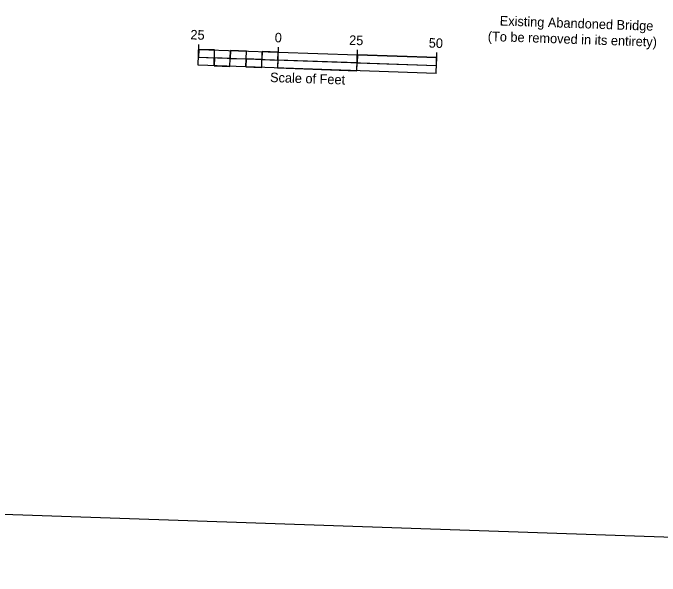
# Model space of a CAD drawing. Extents: x 2191309 to 2193046, y 863659 to 865133.
# Drawn here: x 2192464.6 to 2192668.4, y 863659.4 to 863836.8 of the extents above; entities that cross this region are included whole.
import ezdxf

# ---------------------------------------------------------------- set-up
doc = ezdxf.new("R2010")
doc.units = 0
for name, color, linetype in [('ANNOTATION', 7, 'Continuous'), ('H_V CONTROLS', 7, 'Continuous'), ('PLOT BOUNDARY', 7, 'Continuous')]:
    doc.layers.add(name, color=color, linetype=linetype)

msp = doc.modelspace()

# ---------------------------------------------------------------- linework, layer by layer
at = {"layer": 'H_V CONTROLS'}
for p, q in [((2192522.97, 863820.29), (2192523.19, 863826.85)), ((2192548.18, 863825.99), (2192547.95, 863819.43)), ((2192523.14, 863825.28), (2192598.1, 863822.71)), ((2192527.97, 863820.12), (2192528.14, 863825.11)), ((2192532.96, 863819.94), (2192533.13, 863824.94)), ((2192537.96, 863819.77), (2192538.13, 863824.77)), ((2192542.96, 863819.6), (2192543.13, 863824.6)), ((2192572.94, 863818.57), (2192573.16, 863825.13)), ((2192597.92, 863817.71), (2192598.15, 863824.27)), ((2192523.05, 863822.79), (2192598.01, 863820.21)), ((2192597.92, 863817.71), (2192522.97, 863820.29))]:
    msp.add_line(p, q, dxfattribs=at)
for points in [[(2192528.05, 863822.61), (2192528.14, 863825.11), (2192523.14, 863825.28), (2192523.05, 863822.79), (2192528.05, 863822.61)], [(2192538.05, 863822.27), (2192538.13, 863824.77), (2192533.13, 863824.94), (2192533.05, 863822.44), (2192538.05, 863822.27)], [(2192543.04, 863822.1), (2192548.04, 863821.93), (2192548.13, 863824.43), (2192543.13, 863824.6), (2192543.04, 863822.1)], [(2192528.05, 863822.61), (2192527.97, 863820.12), (2192532.96, 863819.94), (2192533.05, 863822.44), (2192528.05, 863822.61)], [(2192538.05, 863822.27), (2192537.96, 863819.77), (2192542.96, 863819.6), (2192543.04, 863822.1), (2192538.05, 863822.27)], [(2192573.02, 863821.07), (2192548.04, 863821.93), (2192547.95, 863819.43), (2192572.94, 863818.57), (2192573.02, 863821.07)], [(2192573.02, 863821.07), (2192598.01, 863820.21), (2192598.1, 863822.71), (2192573.11, 863823.57), (2192573.02, 863821.07)]]:
    msp.add_lwpolyline(points, dxfattribs=at)
at = {"layer": 'PLOT BOUNDARY'}
msp.add_lwpolyline([(2193027.49, 863659.44), (2192277.93, 863685.16), (2192295.94, 864209.86), (2193045.5, 864184.13)], close=True, dxfattribs=at)

# ---------------------------------------------------------------- texts
at = {"layer": 'ANNOTATION'}
for s, p in [('Existing Abandoned Bridge', (2192617.89, 863832.82)), ('(To be removed in its entirety)', (2192614.12, 863827.94))]:
    msp.add_text(s, height=3, rotation=358.0343, dxfattribs=at).set_placement(p)
at = {"layer": 'H_V CONTROLS'}
for s, p in [('25', (2192520.48, 863828.44)), ('0', (2192547.03, 863827.53)), ('25', (2192570.45, 863826.73)), ('50', (2192595.53, 863825.86)), ('Scale of Feet', (2192545.55, 863815.01))]:
    msp.add_text(s, height=3, rotation=358.0343, dxfattribs=at).set_placement(p)

doc.saveas('drawing.dxf')
